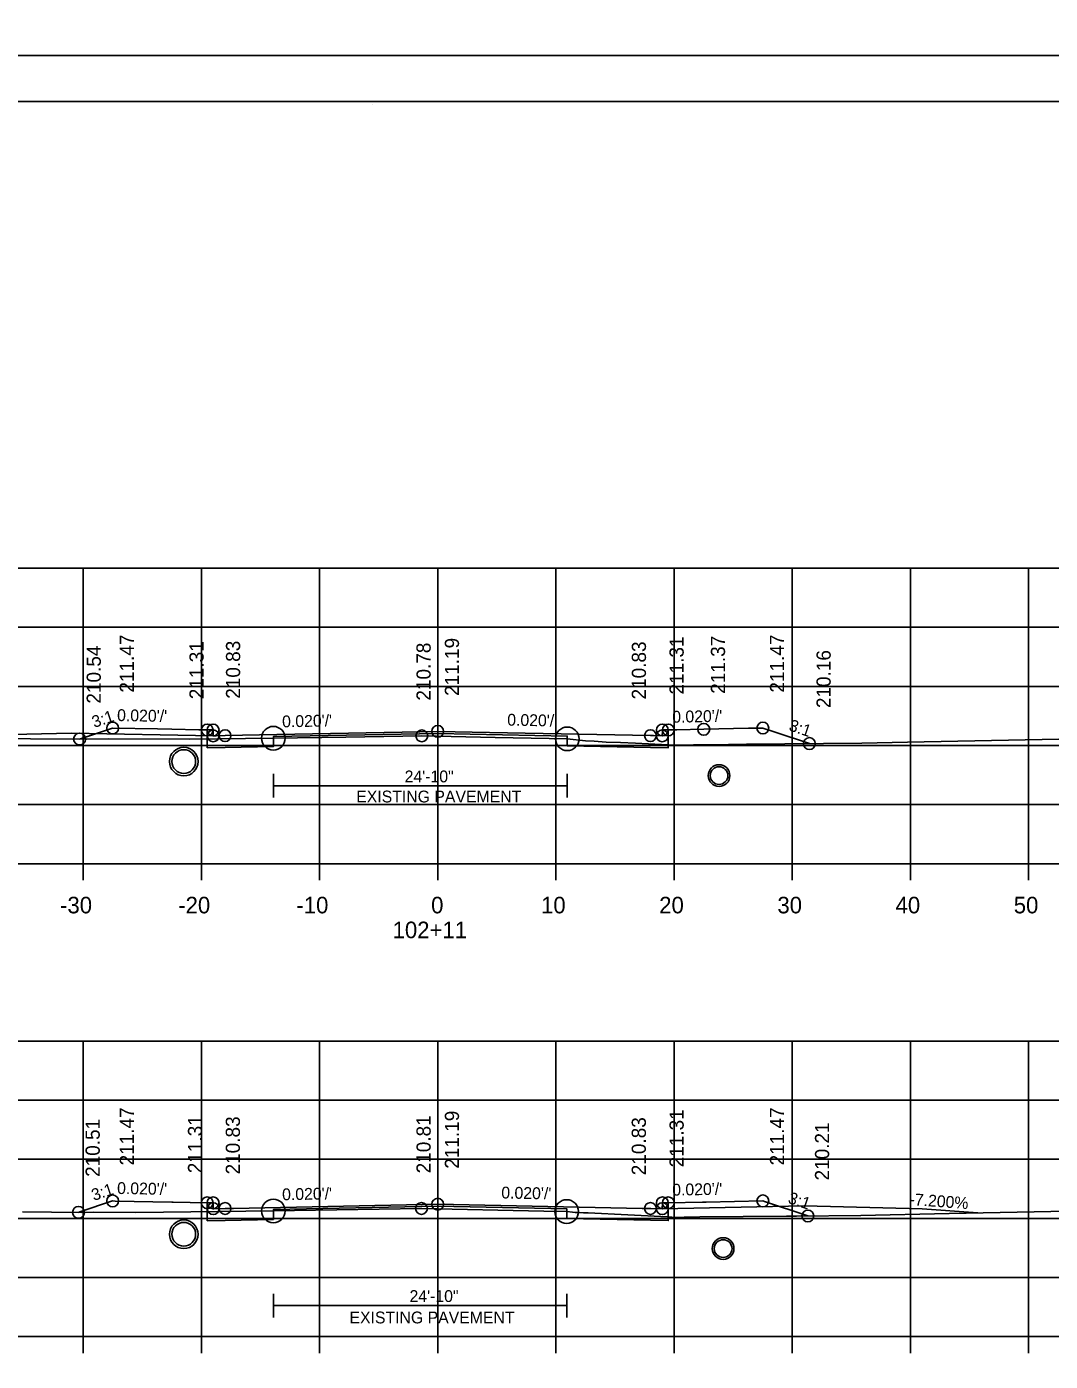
# Model space of a CAD drawing. Extents: x 1368968 to 1369915, y 377395 to 380381.
# Drawn here: x 1369103.3 to 1369190, y 377937.3 to 378050.1 of the extents above; entities that cross this region are included whole.
import ezdxf

# ---------------------------------------------------------------- set-up
doc = ezdxf.new("R2010")
doc.units = 0
for name, color, linetype in [('Default', 7, 'Continuous'), ('S_BORDER_NO_PLOT', 7, 'Continuous'), ('S_BREAKLINE_ANNOT', 7, 'Continuous'), ('S_BRIDGE', 7, 'Continuous'), ('S_BRIDGE_ANNOT', 7, 'Continuous'), ('S_CROSS_DRAIN', 7, 'Continuous'), ('S_CTL_TABLE', 7, 'Continuous'), ('S_CURB_ANNOT', 7, 'Continuous'), ('S_DITCHLINE_ANNOT', 7, 'Continuous'), ('S_DROP_INLET', 7, 'Continuous'), ('S_EXIST_ROW_ANNOT', 7, 'Continuous'), ('S_EXISTING_ALIGNMENT_ANNOT', 7, 'Continuous'), ('S_FENCE', 7, 'Continuous')]:
    doc.layers.add(name, color=color, linetype=linetype)

msp = doc.modelspace()

# ---------------------------------------------------------------- linework, layer by layer
at = {"layer": 'Default'}
for p, q in [((1369149.09, 377990.15), (1369149.09, 377989.32)), ((1369149.04, 377950.16), (1369149.04, 377949.33))]:
    msp.add_line(p, q, dxfattribs=at)
at = {"layer": 'S_BORDER_NO_PLOT'}
for points in [[(1369118.62, 377990.66), (1369118.63, 377989.15), (1369120.13, 377989.18), (1369124.22, 377989.26), (1369124.22, 377990.1), (1369138.13, 377990.37), (1369149.09, 377990.15), (1369149.09, 377989.32), (1369156.13, 377989.18), (1369157.63, 377989.15), (1369157.64, 377990.66)], [(1369118.62, 377950.67), (1369118.63, 377949.15), (1369120.13, 377949.18), (1369124.22, 377949.27), (1369124.22, 377950.1), (1369138.13, 377950.38), (1369149.04, 377950.16), (1369149.04, 377949.33), (1369156.13, 377949.19), (1369157.63, 377949.16), (1369157.64, 377950.67)]]:
    msp.add_lwpolyline(points, dxfattribs=at)
at = {"layer": 'S_BREAKLINE_ANNOT'}
for p, q in [((1368998.13, 377979.35), (1369278.13, 377979.35)), ((1369108.13, 377977.95), (1369108.13, 377979.35)), ((1369118.13, 377977.95), (1369118.13, 377979.35)), ((1369128.13, 377977.95), (1369128.13, 377979.35)), ((1369138.13, 377977.95), (1369138.13, 377979.35)), ((1369148.13, 377977.95), (1369148.13, 377979.35)), ((1369158.13, 377977.95), (1369158.13, 377979.35)), ((1369168.13, 377977.95), (1369168.13, 377979.35)), ((1369178.13, 377977.95), (1369178.13, 377979.35)), ((1369188.13, 377977.95), (1369188.13, 377979.35)), ((1368998.13, 377939.35), (1369278.13, 377939.35)), ((1369108.13, 377937.95), (1369108.13, 377939.35)), ((1369118.13, 377937.95), (1369118.13, 377939.35)), ((1369128.13, 377937.95), (1369128.13, 377939.35)), ((1369138.13, 377937.95), (1369138.13, 377939.35)), ((1369148.13, 377937.95), (1369148.13, 377939.35)), ((1369158.13, 377937.95), (1369158.13, 377939.35)), ((1369168.13, 377937.95), (1369168.13, 377939.35)), ((1369178.13, 377937.95), (1369178.13, 377939.35)), ((1369188.13, 377937.95), (1369188.13, 377939.35))]:
    msp.add_line(p, q, dxfattribs=at)
at = {"layer": 'S_BRIDGE_ANNOT'}
for p, q in [((1368980.13, 378043.81), (1369296.31, 378043.81)), ((1369132.65, 378043.55), (1369132.65, 378043.55)), ((1369132.65, 378043.55), (1369132.65, 378043.55))]:
    msp.add_line(p, q, dxfattribs=at)
at = {"layer": 'S_CROSS_DRAIN'}
for p, q in [((1369097.14, 377990.14), (1369107.14, 377990.4)), ((1369107.14, 377990.4), (1369119.13, 377990.16)), ((1369124.22, 377985.94), (1369149.09, 377985.94)), ((1369169.13, 377950.41), (1369157.13, 377950.17)), ((1369179.13, 377950.15), (1369169.13, 377950.41)), ((1369183.83, 377949.81), (1369179.13, 377950.15)), ((1369124.22, 377941.98), (1369149.04, 377941.98))]:
    msp.add_line(p, q, dxfattribs=at)
at = {"layer": 'S_CTL_TABLE'}
for points in [[(1369099.07, 377989.97), (1369103.68, 377989.92), (1369108.42, 377989.88), (1369110.28, 377989.9), (1369117.11, 377989.88), (1369124.22, 377989.96), (1369130.35, 377990.06), (1369136.78, 377990.16), (1369142.99, 377990.03), (1369149.09, 377989.91), (1369150.63, 377989.75), (1369151.36, 377989.7), (1369152.37, 377989.64), (1369153.59, 377989.59), (1369154.85, 377989.54), (1369157.06, 377989.42), (1369158.34, 377989.38), (1369158.57, 377989.38), (1369159.77, 377989.41), (1369160.01, 377989.41), (1369162.74, 377989.44), (1369164.25, 377989.47), (1369174.02, 377989.55), (1369177.89, 377989.64), (1369203.48, 377990.14)], [(1369103, 377949.91), (1369105.45, 377949.88), (1369107.97, 377949.86), (1369108.96, 377949.87), (1369112.59, 377949.86), (1369124.22, 377949.98), (1369126.02, 377950.01), (1369136.75, 377950.19), (1369147.11, 377949.96), (1369149.04, 377949.93), (1369149.52, 377949.88), (1369149.75, 377949.86), (1369150.07, 377949.84), (1369150.46, 377949.82), (1369150.85, 377949.81), (1369157.58, 377949.47), (1369158.3, 377949.44), (1369158.99, 377949.45), (1369159.68, 377949.46), (1369160.3, 377949.47), (1369167.64, 377949.53), (1369168.48, 377949.55), (1369173.93, 377949.6), (1369181.41, 377949.76), (1369197.2, 377950.07)]]:
    msp.add_lwpolyline(points, dxfattribs=at)
at = {"layer": 'S_CURB_ANNOT'}
for points in [[(1369107.82, 377989.89), (1369108.5, 377990.12), (1369110.62, 377990.82), (1369114.41, 377990.75), (1369115.62, 377990.72), (1369117.9, 377990.68), (1369118.62, 377990.66), (1369119, 377990.66), (1369119.12, 377990.66), (1369119.13, 377990.54), (1369119.13, 377990.16), (1369119.38, 377990.17), (1369120.13, 377990.18), (1369124.5, 377990.27), (1369138.13, 377990.54), (1369142.5, 377990.46), (1369156.13, 377990.18), (1369156.38, 377990.18), (1369157.13, 377990.16), (1369157.14, 377990.54), (1369157.14, 377990.66), (1369157.52, 377990.66), (1369157.64, 377990.66), (1369158.37, 377990.68), (1369160.64, 377990.72), (1369164.43, 377990.8), (1369165.64, 377990.82), (1369166.59, 377990.51), (1369169.58, 377989.51)], [(1369107.73, 377949.86), (1369107.84, 377949.9), (1369110.62, 377950.83), (1369110.82, 377950.82), (1369115.62, 377950.73), (1369115.74, 377950.72), (1369118.62, 377950.67), (1369119.1, 377950.67), (1369119.12, 377950.67), (1369119.13, 377950.19), (1369119.13, 377950.17), (1369119.17, 377950.17), (1369120.13, 377950.19), (1369120.84, 377950.2), (1369138.13, 377950.55), (1369155.43, 377950.2), (1369156.13, 377950.19), (1369156.17, 377950.19), (1369157.13, 377950.17), (1369157.14, 377950.65), (1369157.14, 377950.67), (1369157.16, 377950.67), (1369157.64, 377950.67), (1369160.53, 377950.72), (1369160.64, 377950.73), (1369160.84, 377950.73), (1369165.64, 377950.83), (1369165.79, 377950.78), (1369169.45, 377949.56)]]:
    msp.add_lwpolyline(points, dxfattribs=at)
at = {"layer": 'S_DITCHLINE_ANNOT'}
for p, q in [((1368998.13, 378004.35), (1369278.13, 378004.35)), ((1369108.13, 377979.35), (1369108.13, 378004.35)), ((1369118.13, 377979.35), (1369118.13, 378004.35)), ((1369128.13, 377979.35), (1369128.13, 378004.35)), ((1369138.13, 377979.35), (1369138.13, 378004.35)), ((1369148.13, 377979.35), (1369148.13, 378004.35)), ((1369158.13, 377979.35), (1369158.13, 378004.35)), ((1369168.13, 377979.35), (1369168.13, 378004.35)), ((1369178.13, 377979.35), (1369178.13, 378004.35)), ((1369188.13, 377979.35), (1369188.13, 378004.35)), ((1368998.13, 377999.35), (1369278.13, 377999.35)), ((1368998.13, 377994.35), (1369278.13, 377994.35)), ((1368998.13, 377989.35), (1369278.13, 377989.35)), ((1368998.13, 377984.35), (1369278.13, 377984.35)), ((1368998.13, 377979.35), (1369278.13, 377979.35)), ((1368998.13, 377964.35), (1369278.13, 377964.35)), ((1369108.13, 377939.35), (1369108.13, 377964.35)), ((1369118.13, 377939.35), (1369118.13, 377964.35)), ((1369128.13, 377939.35), (1369128.13, 377964.35)), ((1369138.13, 377939.35), (1369138.13, 377964.35)), ((1369148.13, 377939.35), (1369148.13, 377964.35)), ((1369158.13, 377939.35), (1369158.13, 377964.35)), ((1369168.13, 377939.35), (1369168.13, 377964.35)), ((1369178.13, 377939.35), (1369178.13, 377964.35)), ((1369188.13, 377939.35), (1369188.13, 377964.35)), ((1368998.13, 377959.35), (1369278.13, 377959.35)), ((1368998.13, 377954.35), (1369278.13, 377954.35)), ((1368998.13, 377949.35), (1369278.13, 377949.35)), ((1368998.13, 377944.35), (1369278.13, 377944.35)), ((1368998.13, 377939.35), (1369278.13, 377939.35))]:
    msp.add_line(p, q, dxfattribs=at)
at = {"layer": 'S_DROP_INLET'}
msp.add_line((1368967.73, 378047.71), (1369301.07, 378047.71), dxfattribs=at)
msp.add_line((1368967.73, 378047.71), (1369301.07, 378047.71), dxfattribs=at)
for points in [[(1368967.73, 378261.05), (1369301.07, 378261.05), (1369301.07, 378047.71), (1368967.73, 378047.71)], [(1368967.73, 378047.71), (1369301.07, 378047.71), (1369301.07, 377834.37), (1368967.73, 377834.37)], [(1369214.05, 378043.81), (1369214.05, 378033.93), (1369249.79, 378033.93), (1369249.79, 378031.01), (1369272.99, 378031.01), (1369272.99, 378006.68), (1369296.31, 378006.68), (1369296.31, 377838.35), (1368980.13, 377838.35), (1368980.13, 378043.81)]]:
    msp.add_lwpolyline(points, close=True, dxfattribs=at)
for centre, radius in [((1369110.62, 377990.82), 0.5), ((1369118.62, 377990.66), 0.5), ((1369119.12, 377990.66), 0.5), ((1369124.22, 377989.96), 1), ((1369138.13, 377990.54), 0.5), ((1369149.09, 377989.91), 1), ((1369157.14, 377990.66), 0.5), ((1369157.64, 377990.66), 0.5), ((1369160.64, 377990.72), 0.5), ((1369165.64, 377990.82), 0.5), ((1369107.82, 377989.89), 0.5), ((1369119.13, 377990.16), 0.5), ((1369120.13, 377990.18), 0.5), ((1369120.13, 377990.18), 0.5), ((1369136.78, 377990.16), 0.5), ((1369156.13, 377990.18), 0.5), ((1369156.13, 377990.18), 0.5), ((1369157.13, 377990.16), 0.5), ((1369169.58, 377989.51), 0.5), ((1369116.64, 377987.99), 1.21), ((1369161.93, 377986.8), 0.917), ((1369110.62, 377950.83), 0.5), ((1369165.64, 377950.83), 0.5), ((1369107.73, 377949.86), 0.5), ((1369118.62, 377950.67), 0.5), ((1369119.12, 377950.67), 0.5), ((1369119.13, 377950.17), 0.5), ((1369120.13, 377950.19), 0.5), ((1369120.13, 377950.19), 0.5), ((1369124.22, 377949.98), 1), ((1369136.75, 377950.19), 0.5), ((1369138.13, 377950.55), 0.5), ((1369149.04, 377949.93), 1), ((1369156.13, 377950.19), 0.5), ((1369156.13, 377950.19), 0.5), ((1369157.13, 377950.17), 0.5), ((1369157.14, 377950.67), 0.5), ((1369157.64, 377950.67), 0.5), ((1369116.64, 377948.01), 1.21), ((1369169.45, 377949.56), 0.5), ((1369162.28, 377946.8), 0.917)]:
    msp.add_circle(centre, radius, dxfattribs=at)
at = {"layer": 'S_EXIST_ROW_ANNOT'}
for p, q in [((1369124.22, 377984.94), (1369124.22, 377986.94)), ((1369149.09, 377984.94), (1369149.09, 377986.94)), ((1369124.22, 377940.98), (1369124.22, 377942.98)), ((1369149.04, 377940.98), (1369149.04, 377942.98))]:
    msp.add_line(p, q, dxfattribs=at)
for centre, radius in [((1369116.64, 377987.99), 1), ((1369161.93, 377986.8), 0.75), ((1369116.64, 377948.01), 1), ((1369162.28, 377946.8), 0.75)]:
    msp.add_circle(centre, radius, dxfattribs=at)
at = {"layer": 'S_EXISTING_ALIGNMENT_ANNOT'}
for p, q in [((1369138.13, 377990.14), (1369138.13, 378000.14)), ((1369138.13, 377950.16), (1369138.13, 377960.16))]:
    msp.add_line(p, q, dxfattribs=at)

# ---------------------------------------------------------------- texts
at = {"layer": 'S_BRIDGE'}
for s, p in [('-30', (1369106.17, 377975.15)), ('-20', (1369116.17, 377975.15)), ('-10', (1369126.17, 377975.15)), ('0', (1369137.57, 377975.15)), ('10', (1369146.87, 377975.15)), ('20', (1369156.87, 377975.15)), ('30', (1369166.87, 377975.15)), ('40', (1369176.87, 377975.15)), ('50', (1369186.87, 377975.15)), ('102+11', (1369134.31, 377973.05))]:
    msp.add_text(s, height=1.4, dxfattribs=at).set_placement(p)
at = {"layer": 'S_CROSS_DRAIN'}
msp.add_text('-7.200%', height=1, rotation=355.8818, dxfattribs=at).set_placement((1369178.03, 377950.49))
at = {"layer": 'S_EXIST_ROW_ANNOT'}
for s, p in [('24\'-10"', (1369135.33, 377986.23)), ('EXISTING PAVEMENT', (1369131.23, 377984.53)), ('24\'-10"', (1369135.74, 377942.28)), ('EXISTING PAVEMENT', (1369130.66, 377940.47))]:
    msp.add_text(s, height=1, dxfattribs=at).set_placement(p)
at = {"layer": 'S_EXISTING_ALIGNMENT_ANNOT'}
for s, p in [('211.47', (1369112.42, 377993.82)), ('211.47', (1369167.44, 377993.82)), ('210.54', (1369109.62, 377992.89)), ('211.31', (1369118.32, 377993.26)), ('210.83', (1369121.41, 377993.3)), ('210.78', (1369137.53, 377993.14)), ('211.19', (1369139.93, 377993.54)), ('210.83', (1369155.75, 377993.24)), ('211.31', (1369158.94, 377993.66)), ('211.37', (1369162.44, 377993.72)), ('210.16', (1369171.38, 377992.51)), ('211.47', (1369112.42, 377953.83)), ('211.31', (1369118.19, 377953.17)), ('210.81', (1369137.53, 377953.16)), ('211.19', (1369139.93, 377953.55)), ('211.31', (1369158.94, 377953.67)), ('211.47', (1369167.44, 377953.83)), ('210.51', (1369109.53, 377952.86)), ('210.83', (1369121.39, 377953.07)), ('210.83', (1369155.74, 377953)), ('210.21', (1369171.25, 377952.56))]:
    msp.add_text(s, height=1.2, rotation=90, dxfattribs=at).set_placement(p)
at = {"layer": 'S_FENCE'}
for s, rotation, p in [('3:1', 18.4263, (1369109.06, 377990.83)), ("0.020'/'", 358.8541, (1369110.99, 377991.42)), ("0.020'/'", 1.1457, (1369124.97, 377990.88)), ("0.020'/'", 358.8542, (1369144, 377991.03)), ("0.020'/'", 1.1458, (1369157.98, 377991.27)), ('3:1', 341.5797, (1369167.77, 377990.64)), ("0.020'/'", 358.8543, (1369110.99, 377951.42)), ("0.020'/'", 1.1457, (1369157.98, 377951.27)), ('3:1', 18.4388, (1369109.02, 377950.82)), ("0.020'/'", 1.1458, (1369124.97, 377950.88)), ("0.020'/'", 358.8543, (1369143.5, 377951.04)), ('3:1', 341.5718, (1369167.7, 377950.67))]:
    msp.add_text(s, height=1, rotation=rotation, dxfattribs=at).set_placement(p)

doc.saveas('drawing.dxf')
